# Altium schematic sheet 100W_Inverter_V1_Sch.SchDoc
size A4
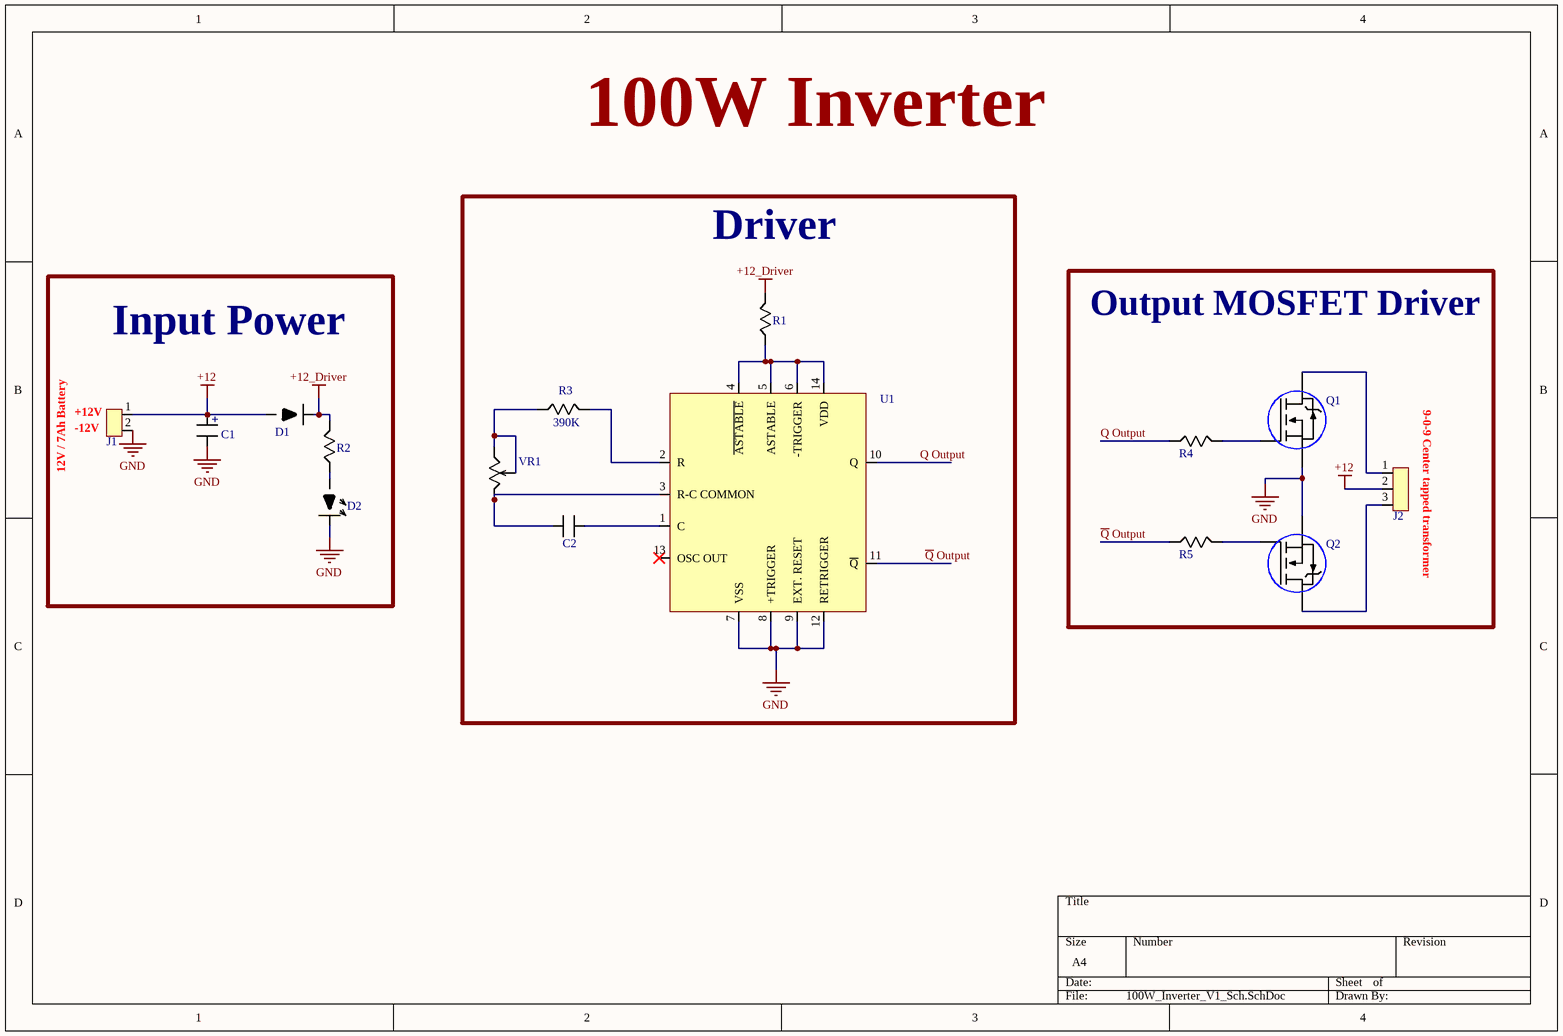
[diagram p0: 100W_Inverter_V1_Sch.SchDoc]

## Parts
C1  C_2200uF_Ely_35V_TH  [Ecap_8mmPitch_16d]  (value not drawn)
C2  C_0.01uF_Cer_50V_TH  [0.01uF_Cer_TH]  (value not drawn)
D1  1N4007  [Diode]  (value not drawn)
D2  LED_3mm_Red_TH  [LED_3MM_Red]  (value not drawn)
J1  TB_2P_5mmP  [TB_5mmP_2Pin]  (value not drawn)
J2  TB_3P_5mmP  [TB_5mmP_3Pin]  (value not drawn)
Q1  IRF540  [TO220]  (value not drawn)
Q2  IRF540  [TO220]  (value not drawn)
R1  R_330_0.25W_TH  [Axial 0.3]  (value not drawn)
R2  R_1K_0.25W_TH  [Axial 0.3]  (value not drawn)
R3  390K  [Axial 0.3]
R4  R_220_0.25W_TH  [Axial 0.3]  (value not drawn)
R5  R_220_0.25W_TH  [Axial 0.3]  (value not drawn)
U1  CD4047BE  [DIP14_8mmspace_2.54mmP]  (value not drawn)
VR1  VR_1K_trim_20T  [3290H]  (value not drawn)

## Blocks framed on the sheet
Driver: C2 R1 R3 U1 VR1
Input Power: C1 D1 D2 J1 R2
Output MOSFET Driver: J2 Q1 Q2 R4 R5

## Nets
+12: C1.1 D1.1 J1.1 J2.2
+12_Driver: D1.2 R1.2 R2.2
GND: C1.2 D2.2 J1.2 Q1.3 Q2.3 U1.7(VSS) U1.8(+TRIGGER) U1.9(EXT._RESET) U1.12(RETRIGGER)
Q Output: R4.1 U1.10(Q)
~{Q} Output: R5.1 U1.11(~{Q})
NetC2_1: C2.1 U1.3(R-C_COMMON) VR1.3
NetC2_2: C2.2 U1.1(C)
NetD2_1: D2.1 R2.1
NetJ2_1: J2.1 Q1.2
NetJ2_3: J2.3 Q2.2
NetQ1_1: Q1.1 R4.2
NetQ2_1: Q2.1 R5.2
NetR1_1: R1.1 U1.4(~{ASTABLE}) U1.5(ASTABLE) U1.6(-TRIGGER) U1.14(VDD)
NetR3_1: R3.1 VR1.1 VR1.2
NetR3_2: R3.2 U1.2(R)

Not connected (* = marked no-connect by the designer): U1 13(OSC_OUT)*

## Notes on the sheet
- 100W Inverter
- (near J1) +12V
- (near J1) -12V
- (near J2) 9-0-9 Center tapped transformer
- (near J1) 12V / 7Ah Battery

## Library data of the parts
C1 = C_2200uF_Ely_35V_TH: Aluminum Electrolytic Capacitor, Polarized, Aluminum (wet), 35V, 20% +Tol, 20% -Tol, 2200uF, Through Hole Mount; Manufacturer 1: CDE Illinois Capacitor; Manufacturer Part Number 1: 228CKR035M; Dielectric Material: Aluminium; ESR (Equivalent Series Resistance): 121mR; Ripple Current: 2.09A; Capacitance: 2.2mF; Polarity: Polar; Life (Hours): 2000Hour
C2 = C_0.01uF_Cer_50V_TH: Capacitor Ceramic 0.01uF 50V C0G 5% 5mm T/R; Manufacturer 1: TDK; Manufacturer Part Number 1: FA28NP01H103JNU06; Capacitance: 10nF; Lead/Base Style: Kinked
D1 = 1N4007: Diode Switching 1KV 1A 2-Pin DO-41 T/R; Manufacturer 1: Diodes; Manufacturer Part Number 1: 1N4007G-T; Max Reverse Current: 5uA; Element Configuration: Single; Max Surge Current: 30A; Reverse Recovery Time: 2us; Polarity: Standard; Capacitance: 8pF; Forward Voltage: 1V
D2 = LED_3mm_Red_TH: Manufacturer 1: SunLED; Manufacturer Part Number 1: XLMDK34D
J1 = TB_2P_5mmP: TERM BLOCK PLUG 2POS 90DEG 5MM; Manufacturer 1: On-Shore Technology; Manufacturer Part Number 1: OSTTH020100; Number of Positions: 2; Number of Levels: 1; Current: 15A; Voltage: 300V; Wire Gauge (Max): 22AWG; Wire Gauge (Min): 14AWG; Pitch: 0.197inch
J2 = TB_3P_5mmP: Res Thick Film 0603 100K Ohm 1% 0.1W(1/10W) ±100ppm/C Pad SMD Automotive T/R; Manufacturer 1: Panasonic; Manufacturer Part Number 1: ERJ3EKF1003V; Voltage Rating: 75V; Resistance: 100kR; Power Rating: 100mW; Temperature Coefficient: 100ppm/°C
Q1 Q2 = IRF540: Mosfet, Power; N-ch; Vdss 100V; Rds(on) 21MILLIOHMS; Id 36A; TO-262; Pd 92W; Vgs +/-20; Manufacturer 1: Infineon; Manufacturer Part Number 1: IRF540ZLPBF; Gate to Source Voltage (Vgs): 20V; Rds On Max: 26.5mR; Input Capacitance: 1.77nF; Turn-Off Delay Time: 43ns; Turn-On Delay Time: 15ns
R1 = R_330_0.25W_TH: TE Connectivity CFR16 Series Axial Carbon Film Resistor 330 5% 0.25W -1200  0ppm/C; Manufacturer Part Number 1: CFR16J330RJIT; Power Rating: 250mW; Resistance: 330R; Temperature Coefficient: 0ppm/°C
R2 = R_1K_0.25W_TH: TE Connectivity CFR16 Series Axial Carbon Film Resistor 1k 5% 0.25W -1200  0ppm/C; Manufacturer Part Number 1: CFR16J1K0; Resistance: 1kR; Temperature Coefficient: 0ppm/°C; Power Rating: 250mW; Voltage Rating: 200V; Number of Resistors: 1
R3 = R_390K_0.25W_TH: RES 390K OHM 1/4W 5% AXIAL; Manufacturer 1: Yageo; Manufacturer Part Number 1: CFR-25JB-52-390K; Resistance: 390kR; Temperature Coefficient: -700ppm/°C; Max Power Dissipation: 250mW
R4 R5 = R_220_0.25W_TH: RES 220 OHM 1/4W 5% AXIAL; Manufacturer 1: Stackpole Electronics; Manufacturer Part Number 1: CF14JT220R; Resistance: 220R; Temperature Coefficient: -400ppm/°C; Max Power Dissipation: 250mW
U1 = CD4047BE: MONO/ASTABLE MULTIVIBRATOR, 125NS, DIP-14; Multivibrator Type:Monostable / Astable; Output Current:6.8A; Supply Voltage Min:3V; Supply Voltage Max:18V; Logic Case Style:DIP; No. of Pins:14; Propagation Delay:125ns; Packaging:Each ;RoHS Compliant: Yes; Manufacturer 1: Texas Instruments; High Level Output Current: -4.2mA; Low Level Output Current: 4.2mA; Quiescent Current: 20uA; Independent Circuits: 1; Output Current: 6.8mA; Min Supply Voltage: 3V; Max Supply Voltage: 18V; Turn-On Delay Time: 300ns; Schmitt Trigger Input: No; Operating Supply Voltage: 12V; Max Power Dissipation: 500mW; Input Capacitance: 5pF
VR1 = VR_1K_trim_20T: TRIMMER 1K OHM 1W PC PIN; Manufacturer 1: Bourns; Manufacturer Part Number 1: 3290H-1-102M; Tolerance: 5%; Resistance: 1kR; Temperature Coefficient: 50ppm/°C; Number of Turns: 25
